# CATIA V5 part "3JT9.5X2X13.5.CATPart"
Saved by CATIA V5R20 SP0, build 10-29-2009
Part number: 3JT9.5X2X13.5
Revision: ANY
Definition: UNKNOWN
Nomenclature: 3JT9.5X2X13.5
Source: Unknown
Bounding box of the stored display mesh (mm): x -6.581 to 6.581, y -1 to 1, z -6.75 to 6.75
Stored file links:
  C:\Users\Utente\Desktop\IO LAVORO\3D X SITO CF\CUMSA\3D files PW\pw081030\pw081030_ejection\3JT9.5X2X13.5.CATPart
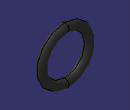
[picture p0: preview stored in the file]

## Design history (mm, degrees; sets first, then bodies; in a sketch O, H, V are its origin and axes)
Body1 "Revolución1" (main body)
  Solid1: solid without history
